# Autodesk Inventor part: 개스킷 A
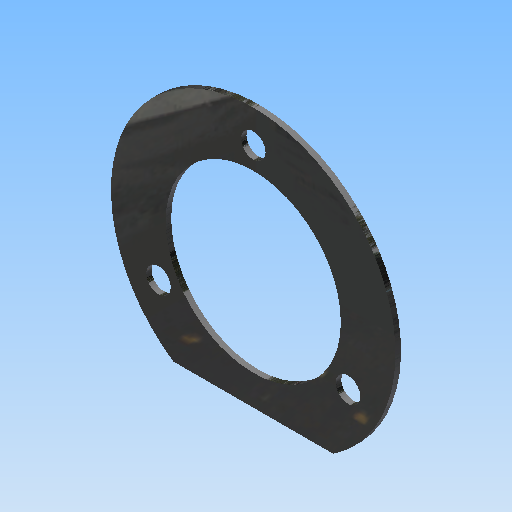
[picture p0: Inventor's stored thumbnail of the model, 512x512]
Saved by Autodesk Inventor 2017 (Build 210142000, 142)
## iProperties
Created: 2020-04
Part Number: 개스킷 A
Material: 고무
Document SubType Name: Modeling
Designer: mduedu
Density: 0.93 g/cm^3
Mass: 1.09963 g
Surface Area: 26.6928 cm^2
Volume: 1.18239 cm^3
Appearance: 고무 - 검은색 - 버전 1.1
Author: mduedu
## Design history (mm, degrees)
sketch "스케치1"
  geometry: C1 r 26 at (0, 0); 1 further point
  constraints: 1 centre point, 1 coincident
  dimensions: "d0" = 52 diameter of C1
extrude "돌출1" new body sketch "스케치1" distance "d1" = 1; taper "d2" = 0 deg
sketch "스케치2"
  geometry: L1 (-14.62, -21.5)-(14.62, -21.5); A1 r 26 centre (0, 0) between (-14.62, -21.5) and (14.62, -21.5) reference; 1 further point
  constraints: 2 end point, 2 point on circle, 1 horizontal
  dimensions: "d3" = 21.5 distance from line of L1 point (0, 0)
extrude "돌출2" cut sketch "스케치2" stored distance "d4" = 1; taper "d5" = 0 deg
sketch "스케치3" dims "d6" = 40
  geometry: 3 further points
  constraints: 2 vertical alignment, 1 coincident, 2 other
hole "구멍1" sketch "스케치3" at (0, 20) diameter "d7" = 4.5; stored, may be unused: countersink angle "d11" = 90 deg, drill point angle "d13" = 118 deg; dims "d8" = 6, "d9" = 4, "d10" = 2, "d12" = 8
sketch "스케치4"
  geometry: C1 r 16 at (0, 0); 1 further point
  constraints: 1 centre point, 1 coincident
  dimensions: "d17" = 32 diameter of C1
extrude "돌출3" cut sketch "스케치4" stored distance "d18" = 1; taper "d19" = 0 deg
node "솔리드1"
pattern_circular "원형 패턴1" dims angle "d15" = 360 deg
node "투영된 루프1"
